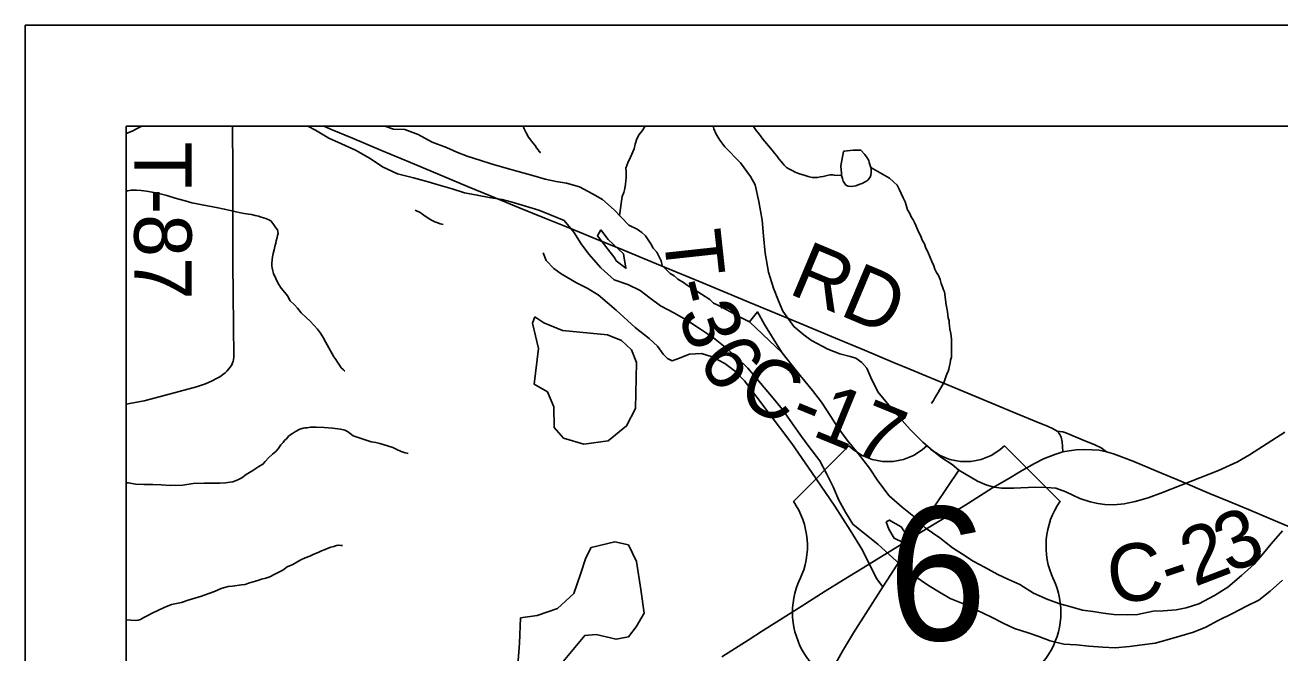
# Model space of a CAD drawing. Extents: x -6.1 to 38, y -7.7 to 22.
# Drawn here: x 2 to 3.241, y 20.379 to 21 of the extents above; entities that cross this region are included whole.
import ezdxf

# ---------------------------------------------------------------- set-up
doc = ezdxf.new("R2010")
doc.units = 0
for name, color, linetype in [('GM_X_Corporation', 7, 'Continuous'), ('GM_X_County_Road', 7, 'Continuous'), ('GM_X_County_Road_Text', 7, 'Continuous'), ('GM_X_Major_River', 7, 'Continuous'), ('GM_X_Minor_Lake', 7, 'Continuous'), ('GM_X_Minor_River', 7, 'Continuous'), ('GM_X_Township_Road', 7, 'Continuous'), ('GM_X_Township_Road_Text', 7, 'Continuous'), ('GM_X_US_Location', 7, 'Continuous'), ('GM_X_US_Route', 7, 'Continuous'), ('GM_X_US_Shield', 7, 'Continuous'), ('SH_Data', 7, 'Continuous')]:
    doc.layers.add(name, color=color, linetype=linetype)

msp = doc.modelspace()

# ---------------------------------------------------------------- linework, layer by layer
at = {"layer": 'GM_X_Corporation'}
msp.add_lwpolyline([(6.9663, 20.9), (2.1, 20.9), (2.1, 19.3655), (3.0705, 19.3761), (3.0991, 19.3766), (3.1097, 19.3768), (3.1203, 19.377), (3.1443, 19.3775), (3.7477, 19.3886), (3.7759, 19.3894), (3.9244, 19.3922), (3.9793, 19.3933), (4.0276, 19.3942), (4.1006, 19.3957), (4.1515, 19.3968), (4.2209, 19.3984), (4.2765, 19.3997)], dxfattribs=at)
msp.add_lwpolyline([(3.3101, 20.9), (2.1, 20.9), (2.1, 20.0941), (2.3478, 20.0866), (2.6192, 20.0796), (3.2913, 20.0587), (3.2911, 20.0669), (3.3039, 20.638)], close=True, dxfattribs=at)
at = {"layer": 'GM_X_County_Road'}
for points in [[(2.2953, 20.9), (2.3035, 20.8966), (2.3237, 20.8881), (2.3524, 20.8761), (2.381, 20.8641), (2.3976, 20.8573), (2.4141, 20.8504), (2.4374, 20.8406), (2.4607, 20.8309), (2.4894, 20.8191), (2.514, 20.8091), (2.5385, 20.7991), (2.5673, 20.7873), (2.591, 20.7777), (2.6147, 20.768), (2.6434, 20.7561), (2.6693, 20.7455), (2.6952, 20.7348), (2.7158, 20.7261), (2.7364, 20.7175), (2.7651, 20.7056), (2.7832, 20.698), (2.8014, 20.6905), (2.8301, 20.6785), (2.8588, 20.6666), (2.8748, 20.6599), (2.8908, 20.6532), (2.9194, 20.6413), (2.9391, 20.6331), (2.9588, 20.6249), (2.9811, 20.6158), (3.0034, 20.6066), (3.011, 20.6034), (3.0165, 20.6008), (3.0204, 20.5986), (3.0217, 20.5973), (3.0231, 20.5953), (3.0244, 20.5926), (3.0254, 20.5881), (3.0259, 20.5835), (3.026, 20.578)], [(3.2458, 20.5976), (3.2106, 20.5751), (3.1988, 20.5683), (3.1801, 20.5596), (3.1246, 20.5378), (3.1106, 20.5328), (3.0976, 20.5291), (3.0868, 20.5268), (3.0766, 20.5256), (3.0678, 20.5261), (3.0608, 20.5271), (3.0531, 20.5288), (3.0428, 20.5321), (3.0291, 20.5386), (3.0193, 20.5423), (3.0096, 20.5428), (2.9988, 20.5431), (2.9776, 20.5423), (2.9656, 20.5421), (2.9581, 20.5431), (2.9511, 20.5451), (2.9418, 20.5493), (2.9233, 20.5601), (2.9003, 20.5256), (2.8561, 20.4568), (2.8481, 20.4448), (2.8192, 20.3992), (2.8083, 20.3812), (2.797, 20.3609)], [(3.0204, 20.5986), (3.026, 20.598), (3.0292, 20.5969), (3.0495, 20.5883), (3.057, 20.5853), (3.0639, 20.582), (3.0694, 20.5782)]]:
    msp.add_lwpolyline(points, dxfattribs=at)
at = {"layer": 'GM_X_Major_River'}
msp.add_line((2.7487, 20.676), (2.7162, 20.7066), dxfattribs=at)
for points in [[(2.2795, 20.9), (2.2871, 20.8961), (2.3003, 20.8882), (2.3128, 20.8825), (2.3268, 20.8765), (2.3412, 20.8682), (2.3533, 20.8599), (2.3684, 20.8531), (2.3839, 20.8489), (2.3987, 20.8452), (2.4085, 20.8421), (2.4222, 20.838), (2.4346, 20.8342), (2.4471, 20.832), (2.4588, 20.8297), (2.4717, 20.8275), (2.4815, 20.8248), (2.4948, 20.8211), (2.508, 20.8169), (2.5201, 20.812), (2.533, 20.8067), (2.5425, 20.7954), (2.5497, 20.7836), (2.5576, 20.7734), (2.5694, 20.7602), (2.5826, 20.7481), (2.5959, 20.7435), (2.6083, 20.7375), (2.6182, 20.7299), (2.6284, 20.7224), (2.642, 20.7152), (2.6553, 20.7076), (2.6678, 20.6993), (2.6806, 20.691), (2.6924, 20.6815), (2.7037, 20.6713), (2.7147, 20.6607), (2.7272, 20.646), (2.7382, 20.6331), (2.7488, 20.6199), (2.7587, 20.6058), (2.7678, 20.5934), (2.775, 20.5835), (2.786, 20.5691), (2.7928, 20.5562), (2.7992, 20.5434), (2.8046, 20.5305), (2.8114, 20.5184), (2.8186, 20.5066), (2.8303, 20.4972), (2.8432, 20.487), (2.8689, 20.4635), (2.8788, 20.4559), (2.8932, 20.4461), (2.9042, 20.4393), (2.9148, 20.4333)], [(2.5969, 20.8022), (2.5825, 20.8174), (2.5711, 20.8277), (2.5609, 20.8333), (2.5481, 20.8401), (2.5352, 20.8439), (2.525, 20.8454), (2.5144, 20.8477), (2.503, 20.851), (2.4875, 20.8552), (2.4735, 20.8593), (2.4607, 20.8627), (2.4508, 20.8661), (2.4372, 20.8703), (2.427, 20.8744), (2.4168, 20.8789), (2.4024, 20.8842), (2.3888, 20.8918), (2.3755, 20.8967), (2.3642, 20.897), (2.3556, 20.9)], [(2.5694, 20.7975), (2.566, 20.7918), (2.583, 20.7697)], [(2.583, 20.7697), (2.5845, 20.767), (2.5941, 20.7597), (2.5918, 20.7738), (2.5766, 20.7881), (2.5694, 20.7975)], [(2.7162, 20.7066), (2.7031, 20.7132), (2.6975, 20.7166), (2.6891, 20.7211), (2.685, 20.723), (2.6808, 20.7252), (2.677, 20.7286), (2.6687, 20.7339), (2.6641, 20.7369), (2.6596, 20.7395), (2.6546, 20.7429), (2.6509, 20.7456), (2.6456, 20.7489), (2.6418, 20.752), (2.638, 20.7546), (2.6338, 20.7584), (2.63, 20.7625), (2.6288, 20.7671), (2.6247, 20.7754), (2.6212, 20.7796), (2.6186, 20.7837), (2.6136, 20.7917), (2.6098, 20.7951), (2.6053, 20.7984), (2.5969, 20.8022)], [(2.7487, 20.676), (2.7408, 20.6885), (2.7313, 20.704), (2.7241, 20.7165), (2.7162, 20.7066)], [(3.2432, 20.5002), (3.2322, 20.4873), (3.2247, 20.4778), (3.2153, 20.4672), (3.2028, 20.4558), (3.1892, 20.4444), (3.176, 20.436), (3.1605, 20.428), (3.148, 20.4238), (3.1382, 20.4219), (3.1254, 20.4208), (3.1155, 20.4207), (3.1, 20.4173), (3.0902, 20.4169), (3.0766, 20.4173), (3.066, 20.4188), (3.0562, 20.4202), (3.0456, 20.4217), (3.0331, 20.4251), (3.0233, 20.4278), (3.0112, 20.4323), (2.9972, 20.4383), (2.9835, 20.447), (2.9718, 20.4523), (2.962, 20.4568), (2.9487, 20.464), (2.9374, 20.4701), (2.9268, 20.4769), (2.9169, 20.4833), (2.9044, 20.4931), (2.8901, 20.503), (2.8806, 20.5128), (2.8673, 20.5234), (2.8545, 20.5348), (2.8431, 20.5495), (2.8351, 20.562), (2.8238, 20.5764), (2.8128, 20.5896), (2.8029, 20.6033), (2.7969, 20.6131), (2.7874, 20.6271), (2.7787, 20.6389), (2.7665, 20.6536), (2.7586, 20.6635), (2.7487, 20.676)], [(2.8731, 20.4882), (2.8719, 20.4958), (2.8662, 20.5041), (2.8582, 20.5087), (2.8548, 20.5107), (2.8515, 20.509)], [(2.8515, 20.509), (2.8541, 20.5018), (2.8594, 20.4927), (2.8682, 20.4885), (2.8731, 20.4882)], [(2.9148, 20.4333), (2.928, 20.428), (2.9412, 20.4216), (2.9549, 20.4151), (2.9677, 20.4083), (2.9783, 20.4034), (2.9919, 20.3993), (3.0025, 20.3955), (3.0135, 20.3914), (3.0271, 20.388), (3.0396, 20.3872), (3.0517, 20.3861), (3.0657, 20.385), (3.0778, 20.3843), (3.0922, 20.3858), (3.1046, 20.3874), (3.1175, 20.3889), (3.1292, 20.3923), (3.1417, 20.3958), (3.1553, 20.4), (3.1674, 20.4049), (3.1798, 20.4114), (3.1938, 20.4182), (3.2078, 20.4255), (3.2199, 20.4315), (3.2312, 20.4403), (3.2433, 20.4513)]]:
    msp.add_lwpolyline(points, dxfattribs=at)
at = {"layer": 'GM_X_Minor_Lake'}
for points in [[(2.8092, 20.8752), (2.8098, 20.8753), (2.8128, 20.8757), (2.8159, 20.8761), (2.8189, 20.8765), (2.8212, 20.8765), (2.8246, 20.8762), (2.8265, 20.8762), (2.8304, 20.8721), (2.8327, 20.8687), (2.8342, 20.866), (2.8346, 20.8641), (2.8354, 20.8622), (2.8362, 20.8592), (2.8366, 20.8565), (2.8366, 20.8546), (2.8363, 20.8516), (2.8356, 20.8497), (2.8333, 20.8466), (2.8314, 20.8455), (2.8295, 20.8443), (2.8276, 20.8435), (2.8254, 20.8427), (2.8216, 20.8412), (2.8193, 20.8408), (2.8167, 20.8404), (2.814, 20.8407), (2.8117, 20.8418), (2.809, 20.8456), (2.8082, 20.8483), (2.8074, 20.8513), (2.8074, 20.8543), (2.807, 20.8566), (2.8065, 20.8608), (2.8092, 20.8752)], [(2.8092, 20.8752), (2.8065, 20.8608), (2.807, 20.8566), (2.8074, 20.8543), (2.8074, 20.8513), (2.8082, 20.8483), (2.809, 20.8456), (2.8117, 20.8418), (2.814, 20.8407), (2.8167, 20.8404), (2.8193, 20.8408), (2.8216, 20.8412), (2.8254, 20.8427), (2.8276, 20.8435), (2.8295, 20.8443), (2.8314, 20.8455), (2.8333, 20.8466), (2.8356, 20.8497)], [(2.8356, 20.8497), (2.8363, 20.8516), (2.8366, 20.8546), (2.8366, 20.8565), (2.8362, 20.8592), (2.8354, 20.8622), (2.8346, 20.8641), (2.8342, 20.866), (2.8327, 20.8687), (2.8304, 20.8721), (2.8265, 20.8762), (2.8246, 20.8762), (2.8212, 20.8765), (2.8189, 20.8765), (2.8159, 20.8761), (2.8128, 20.8757), (2.8098, 20.8753), (2.8092, 20.8752)], [(2.5041, 20.7116), (2.5018, 20.7052), (2.5077, 20.6802), (2.5034, 20.6449), (2.5166, 20.6374), (2.5228, 20.6227), (2.5233, 20.6022), (2.5324, 20.5916), (2.5525, 20.5857), (2.5767, 20.5889), (2.5947, 20.6038), (2.6036, 20.6209)], [(2.6036, 20.6209), (2.6045, 20.6664), (2.5995, 20.6789), (2.5896, 20.6883), (2.576, 20.6939), (2.5313, 20.6982), (2.5128, 20.7056), (2.5041, 20.7116)], [(2.5647, 20.3977), (2.5844, 20.3929), (2.5968, 20.3953), (2.6043, 20.4052), (2.6122, 20.4185), (2.609, 20.442), (2.6047, 20.4696), (2.5966, 20.4863), (2.583, 20.4892), (2.5596, 20.4834), (2.5544, 20.4735), (2.5492, 20.4572), (2.5425, 20.4382), (2.5264, 20.4233), (2.5064, 20.4163), (2.4898, 20.414)], [(2.4898, 20.414), (2.4888, 20.3889), (2.4857, 20.3457), (2.4889, 20.3268), (2.503, 20.3098), (2.5193, 20.3012), (2.516, 20.3387), (2.5204, 20.3569), (2.5534, 20.3965), (2.5647, 20.3977)]]:
    msp.add_lwpolyline(points, dxfattribs=at)
at = {"layer": 'GM_X_Minor_River'}
for points in [[(2.1, 20.893), (2.1059, 20.8953), (2.1115, 20.898), (2.1149, 20.8999), (2.1152, 20.9)], [(2.4925, 20.9), (2.4936, 20.8976), (2.4956, 20.8934), (2.4979, 20.8893), (2.5002, 20.8863), (2.5021, 20.8836), (2.5044, 20.881), (2.5056, 20.8787), (2.5072, 20.8768), (2.5083, 20.8749), (2.5095, 20.8742), (2.5091, 20.8742)], [(2.5879, 20.8117), (2.5904, 20.8306), (2.5919, 20.8344), (2.593, 20.8386), (2.5937, 20.8428), (2.5945, 20.8492), (2.5944, 20.8549), (2.5941, 20.8587), (2.5959, 20.864), (2.5985, 20.8693), (2.6023, 20.8777), (2.6034, 20.8822), (2.6049, 20.8875), (2.6071, 20.8917), (2.6101, 20.8955), (2.6131, 20.9)], [(2.72, 20.9), (2.7209, 20.8987), (2.7229, 20.8957), (2.7252, 20.8931), (2.7271, 20.8904), (2.7294, 20.8874), (2.7314, 20.8848), (2.7387, 20.8765), (2.741, 20.8735), (2.7433, 20.8708), (2.7452, 20.8678), (2.7476, 20.8652), (2.7506, 20.8614), (2.7529, 20.8591), (2.7552, 20.858), (2.7572, 20.8569)], [(2.8362, 20.8592), (2.8546, 20.8487), (2.8588, 20.845), (2.8623, 20.8416), (2.8642, 20.8378), (2.8662, 20.8336), (2.8681, 20.8291), (2.8701, 20.8253), (2.8712, 20.8219), (2.8724, 20.8174), (2.8748, 20.8136), (2.8763, 20.8105), (2.8782, 20.8075), (2.8798, 20.8041), (2.8837, 20.795), (2.8857, 20.7913), (2.8872, 20.7875), (2.8892, 20.7837), (2.8907, 20.7795), (2.8927, 20.7757), (2.895, 20.7704), (2.8966, 20.7663), (2.8985, 20.7621), (2.8997, 20.7587), (2.9013, 20.7553), (2.9032, 20.7523), (2.9048, 20.7485), (2.906, 20.7447), (2.9071, 20.7413), (2.9083, 20.7383), (2.9091, 20.7364), (2.9108, 20.7235), (2.9116, 20.72), (2.912, 20.7166), (2.9124, 20.7136), (2.9128, 20.7105), (2.9136, 20.7075), (2.9136, 20.7052), (2.9141, 20.7026), (2.9145, 20.6995), (2.9153, 20.695), (2.9157, 20.6923), (2.9161, 20.6897), (2.9161, 20.6874), (2.9162, 20.6851), (2.9162, 20.6828), (2.9162, 20.6802), (2.9162, 20.6779), (2.9159, 20.6748), (2.9159, 20.6718), (2.9152, 20.6687), (2.9149, 20.6657), (2.9141, 20.663), (2.9134, 20.66), (2.9127, 20.6577), (2.9119, 20.6558), (2.9105, 20.6524), (2.9097, 20.6504), (2.909, 20.6482), (2.9075, 20.6447), (2.9045, 20.6397), (2.903, 20.6367), (2.9012, 20.634), (2.8993, 20.631), (2.8982, 20.629), (2.8967, 20.6267), (2.8959, 20.6264)], [(2.7572, 20.8569), (2.7591, 20.8558), (2.7614, 20.8546), (2.7648, 20.8532), (2.7682, 20.8524), (2.7713, 20.8513), (2.7743, 20.8502), (2.7782, 20.8495), (2.7816, 20.8495), (2.7835, 20.8495), (2.7865, 20.85), (2.7892, 20.8504), (2.793, 20.8512), (2.796, 20.852), (2.7987, 20.852), (2.8002, 20.8516), (2.8074, 20.8513)], [(2.1, 20.8363), (2.1016, 20.8363), (2.105, 20.8367), (2.11, 20.8368), (2.1149, 20.8364), (2.1202, 20.8357), (2.1256, 20.835), (2.1321, 20.8335), (2.1401, 20.8317), (2.1485, 20.8288), (2.1584, 20.8262), (2.1649, 20.8244), (2.1702, 20.8233), (2.1751, 20.8222), (2.1908, 20.8193), (2.1969, 20.8182), (2.203, 20.8168), (2.2087, 20.8153), (2.2148, 20.8142), (2.2209, 20.8131), (2.2239, 20.8128), (2.2274, 20.8117), (2.2308, 20.811), (2.2335, 20.8102), (2.2357, 20.8095), (2.238, 20.8088), (2.2411, 20.8076), (2.243, 20.8065), (2.2461, 20.8027), (2.248, 20.7997), (2.2496, 20.7975), (2.2504, 20.794), (2.2496, 20.7921), (2.2493, 20.7899), (2.2482, 20.7868), (2.2478, 20.7845), (2.2471, 20.7811), (2.2464, 20.7777), (2.2453, 20.7742), (2.2446, 20.7708), (2.2442, 20.7678), (2.2439, 20.7647), (2.2439, 20.7617), (2.2447, 20.7583), (2.2455, 20.7545), (2.2478, 20.7495), (2.2502, 20.7446), (2.2533, 20.7401), (2.2567, 20.7356), (2.2594, 20.7322), (2.2622, 20.7273), (2.2664, 20.7235), (2.2695, 20.7201), (2.2729, 20.7156), (2.2779, 20.7111), (2.2818, 20.7073), (2.2856, 20.7035), (2.2891, 20.6994), (2.2922, 20.6956), (2.2949, 20.6911), (2.2972, 20.6869), (2.3054, 20.6722), (2.3073, 20.6695), (2.3089, 20.6669)], [(2.3858, 20.8171), (2.3908, 20.8148), (2.3942, 20.8122), (2.3985, 20.8092), (2.4019, 20.807), (2.405, 20.8055), (2.408, 20.8044), (2.4103, 20.8036), (2.4122, 20.8033), (2.4134, 20.8029)], [(2.3089, 20.6669), (2.3108, 20.6639), (2.3127, 20.6612), (2.3147, 20.6593), (2.3158, 20.6582), (2.3162, 20.6582)], [(2.1, 20.5475), (2.1023, 20.5474), (2.1092, 20.5463), (2.1175, 20.546), (2.1263, 20.5457), (2.1346, 20.5454), (2.1434, 20.5447), (2.1559, 20.5452), (2.1662, 20.5468), (2.1772, 20.5473), (2.1856, 20.547), (2.1924, 20.5471), (2.1981, 20.5475), (2.2027, 20.548), (2.2053, 20.5484), (2.2072, 20.5492), (2.2102, 20.5503), (2.2144, 20.5523), (2.2185, 20.5557), (2.2253, 20.5596), (2.231, 20.5635), (2.2352, 20.5658), (2.2374, 20.5685), (2.2408, 20.5723), (2.2445, 20.5758), (2.2479, 20.5785), (2.2502, 20.5811), (2.2528, 20.585), (2.2551, 20.5873), (2.2565, 20.5892), (2.2584, 20.5911), (2.2607, 20.5938), (2.2645, 20.5961), (2.2675, 20.5984), (2.2716, 20.6004), (2.275, 20.6015), (2.2769, 20.6019), (2.2788, 20.602), (2.2822, 20.6024), (2.2879, 20.6024), (2.2956, 20.6021), (2.3039, 20.6014), (2.3119, 20.6004), (2.3161, 20.5997), (2.3188, 20.5982), (2.3215, 20.5963), (2.3245, 20.594), (2.3284, 20.5926), (2.3421, 20.5881), (2.3467, 20.5874), (2.3509, 20.5863), (2.3585, 20.5841), (2.3635, 20.5823), (2.3677, 20.5804), (2.3719, 20.5786), (2.3757, 20.5771), (2.378, 20.5767), (2.3783, 20.5763)], [(2.205, 20.4453), (2.2141, 20.4466), (2.2175, 20.447), (2.2209, 20.4482), (2.2255, 20.4497), (2.23, 20.4509), (2.2338, 20.4521), (2.238, 20.4533), (2.2421, 20.4545), (2.2463, 20.4568), (2.2508, 20.4591), (2.255, 20.461), (2.2591, 20.4645), (2.2648, 20.4668), (2.2686, 20.4692), (2.2727, 20.4715), (2.2769, 20.4734), (2.2814, 20.475), (2.2856, 20.4769), (2.2898, 20.4785), (2.2932, 20.4804), (2.2966, 20.4816), (2.2996, 20.4828), (2.3022, 20.484), (2.3053, 20.4847), (2.3079, 20.4855), (2.3083, 20.4855), (2.3102, 20.4859), (2.3121, 20.4856), (2.314, 20.4856)], [(2.1, 20.412), (2.1001, 20.412), (2.1046, 20.4116), (2.1088, 20.4113), (2.1119, 20.4117), (2.1141, 20.4125), (2.1168, 20.4141), (2.1206, 20.416), (2.1255, 20.4187), (2.1311, 20.4214), (2.1376, 20.4241), (2.1448, 20.4273), (2.1546, 20.4293), (2.1611, 20.4316), (2.1679, 20.4336), (2.1743, 20.4355), (2.1808, 20.4379), (2.1872, 20.4402), (2.194, 20.443), (2.2008, 20.4449), (2.205, 20.4453)]]:
    msp.add_lwpolyline(points, dxfattribs=at)
at = {"layer": 'GM_X_Township_Road'}
for points in [[(2.1, 20.6252), (2.1178, 20.6286), (2.1437, 20.6354), (2.1696, 20.6423), (2.1784, 20.6454), (2.1849, 20.6483), (2.1893, 20.6505), (2.1925, 20.6523), (2.1951, 20.6541), (2.1977, 20.6563), (2.1995, 20.658), (2.2015, 20.6601), (2.2038, 20.6633), (2.2044, 20.6643), (2.2052, 20.6661), (2.2056, 20.6677), (2.206, 20.6692), (2.2063, 20.6719), (2.206, 20.703), (2.2058, 20.7341), (2.2055, 20.7641), (2.2053, 20.794), (2.2054, 20.8251), (2.2055, 20.8562), (2.2052, 20.9)], [(2.9233, 20.5601), (2.9168, 20.5656), (2.9066, 20.5723), (2.8971, 20.5798), (2.8876, 20.5876), (2.8753, 20.6001), (2.8621, 20.6151), (2.8523, 20.6263), (2.8433, 20.6376), (2.8363, 20.6516), (2.8323, 20.6608), (2.8273, 20.6663), (2.8213, 20.6706), (2.8158, 20.6723), (2.8055, 20.6751), (2.7937, 20.6796), (2.7777, 20.6881), (2.7702, 20.6938), (2.7603, 20.7021), (2.7494, 20.7171), (2.7449, 20.7273), (2.74, 20.7398), (2.735, 20.7558), (2.7318, 20.7746), (2.73, 20.7918), (2.7288, 20.8071), (2.7255, 20.8256), (2.7218, 20.8421), (2.7173, 20.8503), (2.7075, 20.8638), (2.692, 20.8796), (2.687, 20.8863), (2.6833, 20.8921), (2.681, 20.8976), (2.6805, 20.9)], [(2.8481, 20.4448), (2.8418, 20.4528), (2.8281, 20.4808), (2.816, 20.5006), (2.8006, 20.5243), (2.7778, 20.5578), (2.7581, 20.5863), (2.7114, 20.6483), (2.7025, 20.6577), (2.692, 20.6656), (2.6795, 20.6721), (2.6688, 20.6754), (2.6569, 20.6747), (2.6461, 20.6704), (2.64, 20.6682), (2.6353, 20.6703), (2.6308, 20.6747), (2.6253, 20.6826), (2.617, 20.6903), (2.6033, 20.7012), (2.5844, 20.7182), (2.5666, 20.7333), (2.5559, 20.7398), (2.5454, 20.7451), (2.5302, 20.7542), (2.5229, 20.7593), (2.5154, 20.7674), (2.5124, 20.7749)]]:
    msp.add_lwpolyline(points, dxfattribs=at)
at = {"layer": 'GM_X_US_Route'}
msp.add_lwpolyline([(2.6888, 20.3755), (2.715, 20.3921), (2.7292, 20.4011), (2.7434, 20.4101), (2.7673, 20.4253), (2.7911, 20.4405), (2.8091, 20.4515), (2.8271, 20.4625), (2.85, 20.4765), (2.8647, 20.4856), (2.8794, 20.4947), (2.8941, 20.5037), (2.9088, 20.5126), (2.9328, 20.5275), (2.9567, 20.5424), (2.971, 20.5509), (2.9852, 20.5595), (2.998, 20.5665), (3.007, 20.5711), (3.0182, 20.5756), (3.026, 20.578), (3.0325, 20.5792), (3.0393, 20.58), (3.0471, 20.5803), (3.055, 20.5802), (3.0621, 20.5797), (3.0694, 20.5782), (3.0764, 20.5761), (3.0841, 20.5733), (3.0965, 20.5686), (3.1196, 20.5588), (3.1427, 20.5491), (3.1713, 20.5371), (3.1905, 20.5291), (3.2096, 20.521), (3.2383, 20.509), (3.2588, 20.5004)], dxfattribs=at)
at = {"layer": 'GM_X_US_Shield'}
for p, q in [((2.8146, 20.5842), (2.7597, 20.5292)), ((3.0234, 20.5292), (2.9684, 20.5842))]:
    msp.add_line(p, q, dxfattribs=at)
for centre, radius, start, end in [((2.8531, 20.6234), 0.0549, 225.573, 314.427), ((2.93, 20.6234), 0.0549, 225.573, 314.427), ((2.6967, 20.4851), 0.0769, 334.5471, 35.0009), ((3.0864, 20.4851), 0.0769, 144.9991, 205.4529), ((2.8357, 20.4194), 0.0769, 154.8319, 270.6383), ((2.9473, 20.4194), 0.0769, 269.3617, 25.1681)]:
    msp.add_arc(centre, radius, start, end, dxfattribs=at)
at = {"layer": 'SH_Data'}
for p, q in [((2, 21), (9, 21)), ((2, 21), (2, 14)), ((2.1, 20.9), (2.1, 14.1)), ((2.1, 20.9), (8.9, 20.9))]:
    msp.add_line(p, q, dxfattribs=at)

# ---------------------------------------------------------------- texts
at = {"layer": 'GM_X_County_Road_Text'}
for s, height, rotation, p in [('RD', 0.05682, 337.1898, (2.7534, 20.7352)), ('C-17', 0.05682, 337.751, (2.7025, 20.6251)), ('3', 0.0568, 22.2499, (3.1903, 20.4574)), ('2', 0.0568, 20.9453, (3.1563, 20.4444)), ('C', 0.0568, 7.4324, (3.0737, 20.4274)), ('-', 0.0568, 18.5783, (3.1317, 20.4361))]:
    msp.add_text(s, height=height, rotation=rotation, dxfattribs=at).set_placement(p)
at = {"layer": 'GM_X_Township_Road_Text'}
for s, height, rotation, p in [('T-87', 0.05682, 270, (2.1079, 20.8848)), ('T', 0.0568, 276.2048, (2.631, 20.7946)), ('-', 0.0568, 283.82, (2.637, 20.7442)), ('3', 0.0568, 290.6288, (2.6448, 20.7145)), ('6', 0.0568, 304.3327, (2.6639, 20.6687))]:
    msp.add_text(s, height=height, rotation=rotation, dxfattribs=at).set_placement(p)
at = {"layer": 'GM_X_US_Location'}
for s in ['0', '/']:
    msp.add_text(s, height=0.000189, dxfattribs=at).set_placement((2.8915, 20.4568))
msp.add_text('6', height=0.000189, rotation=0, dxfattribs=at).set_placement((2.8724, 20.4176))
at = {"layer": 'GM_X_US_Shield'}
msp.add_text('6', height=0.1318, dxfattribs=at).set_placement((2.8532, 20.3919))

doc.saveas('drawing.dxf')
